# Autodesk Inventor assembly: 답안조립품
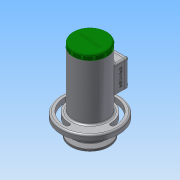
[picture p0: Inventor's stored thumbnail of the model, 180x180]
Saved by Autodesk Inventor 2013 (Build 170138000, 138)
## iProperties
Created: 2017-05
Part Number: 답안조립품
Document SubType Name: Assembly
Designer: Administrator
Author: Administrator
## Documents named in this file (20)
- C:\Users\Administrator\Desktop\470508V1019\답안조립품.iam
- C:\Users\Administrator\Desktop\470508V1019\본체.ipt
- C:\Users\Administrator\Desktop\470508V1019\V-벨트풀리.ipt
- C:\Users\Administrator\Desktop\470508V1019\너트 M10.ipt
- C:\Users\Administrator\Desktop\470508V1019\멈춤링 15 x 1.ipt
- C:\Users\Administrator\Desktop\470508V1019\멈춤링 35x1.6.ipt
- C:\Users\Administrator\Desktop\470508V1019\베어링 15 x 35 x 11.ipt
- C:\Users\Administrator\Desktop\470508V1019\볼트 M4 x 10.ipt
- C:\Users\Administrator\Desktop\470508V1019\부시1.ipt
- C:\Users\Administrator\Desktop\470508V1019\부시2.ipt
- C:\Users\Administrator\Desktop\470508V1019\사이드 커버.ipt
- 사이드 커버.ipt
- C:\Users\Administrator\Desktop\470508V1019\십자볼트 M3 x 10.ipt
- C:\Users\Administrator\Desktop\470508V1019\오일 실 15 25 7.ipt
- C:\Users\Administrator\Desktop\470508V1019\와셔 3x6.ipt
- C:\Users\Administrator\Desktop\470508V1019\와셔 4x16.ipt
- C:\Users\Administrator\Desktop\470508V1019\와셔 10x21.ipt
- C:\Users\Administrator\Desktop\470508V1019\축.ipt
- C:\Users\Administrator\Desktop\470508V1019\키 4 x 4 x 18.ipt
- C:\Users\Administrator\Desktop\470508V1019\탑 커버.ipt
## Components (2 placed, 2 different names)
1. V-벨트풀리:1
2. ISO 4017 M4 x 10:1
